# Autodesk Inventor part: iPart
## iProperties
Created: 2002-11
Part Number: iPart
Material: Default
Document SubType Name: Modeling
Designer: ***
Density: 1 g/cm^3
Author: ***
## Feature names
1. Derived Body1 [Tagging]
